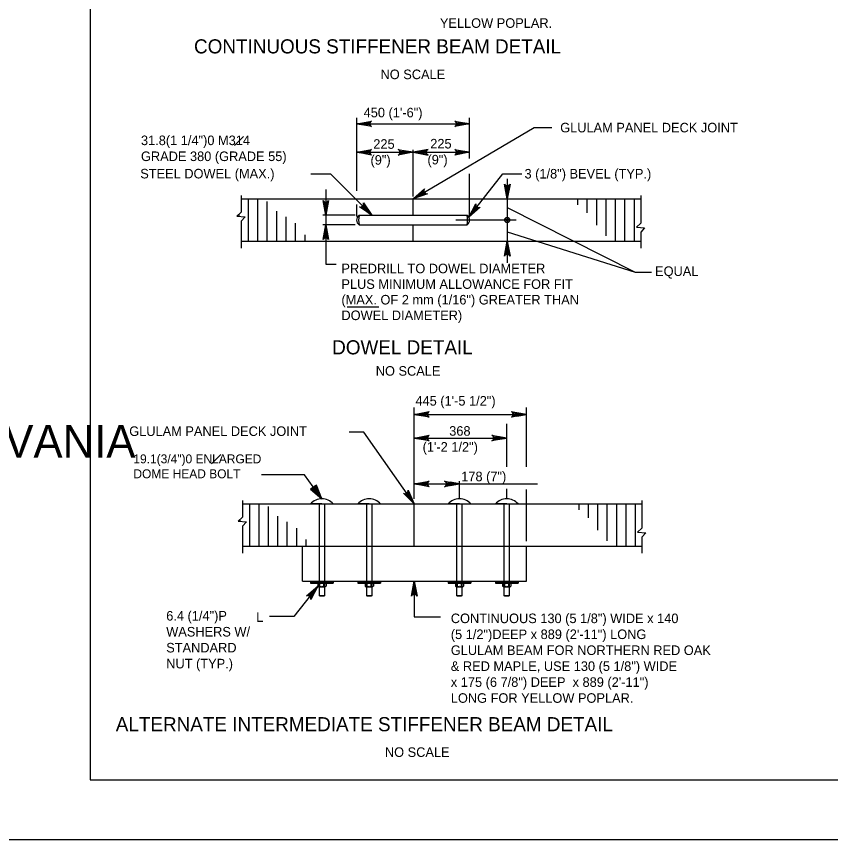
# Model space of a CAD drawing. Extents: x -8 to 75, y -110 to 0.
# Drawn here: x 34.83 to 45.04, y -88 to -77.67 of the extents above; entities that cross this region are included whole.
import ezdxf

# ---------------------------------------------------------------- set-up
doc = ezdxf.new("R2010")
doc.units = 0
for name, color, linetype in [('1', 7, 'Continuous'), ('2', 7, 'Continuous'), ('3', 7, 'Continuous'), ('5', 7, 'Continuous'), ('63', 7, 'Continuous')]:
    doc.layers.add(name, color=color, linetype=linetype)

msp = doc.modelspace()

# ---------------------------------------------------------------- linework, layer by layer
at = {"layer": '1'}
msp.add_lwpolyline([(35.75, -87.25), (67.25, -87.25), (67.25, -66.75), (35.75, -66.75)], close=True, dxfattribs=at)
at = {"layer": '2'}
for p, q in [((37.647, -79.916), (37.647, -80.126)), ((42.661, -79.916), (42.661, -80.264)), ((37.647, -79.959), (42.661, -79.959)), ((39.804, -80.166), (39.804, -79.959)), ((37.647, -80.126), (37.592, -80.178)), ((37.592, -80.178), (37.696, -80.184)), ((37.696, -80.184), (37.647, -80.239)), ((37.647, -80.239), (37.647, -80.579)), ((39.804, -80.491), (39.804, -80.284)), ((42.661, -80.264), (42.606, -80.316)), ((42.606, -80.316), (42.71, -80.322)), ((42.71, -80.322), (42.661, -80.376)), ((42.661, -80.376), (42.661, -80.579)), ((37.647, -80.491), (42.661, -80.491)), ((38.442, -83.422), (37.899, -83.422)), ((38.659, -83.723), (38.442, -83.422)), ((37.662, -83.743), (37.662, -83.954)), ((42.676, -83.743), (42.676, -84.091)), ((37.662, -83.787), (42.676, -83.787)), ((38.659, -83.787), (38.517, -83.787)), ((38.628, -84.94), (38.628, -83.787)), ((38.659, -83.787), (38.802, -83.787)), ((38.691, -83.787), (38.691, -84.94)), ((39.221, -84.94), (39.221, -83.787)), ((39.284, -83.787), (39.284, -84.94)), ((39.819, -84.319), (39.819, -83.787)), ((40.354, -84.94), (40.354, -83.787)), ((40.417, -83.787), (40.417, -84.94)), ((40.948, -84.94), (40.948, -83.787)), ((41.011, -83.787), (41.011, -84.94)), ((37.662, -83.954), (37.607, -84.006)), ((37.607, -84.006), (37.711, -84.012)), ((37.711, -84.012), (37.662, -84.066)), ((37.662, -84.066), (37.662, -84.407)), ((42.676, -84.091), (42.621, -84.144)), ((42.621, -84.144), (42.725, -84.149)), ((42.725, -84.149), (42.676, -84.204)), ((42.676, -84.204), (42.676, -84.407)), ((37.662, -84.319), (42.676, -84.319)), ((38.414, -84.759), (38.414, -84.319)), ((41.225, -84.759), (41.225, -84.319)), ((38.414, -84.759), (41.225, -84.759)), ((38.711, -84.783), (38.607, -84.783)), ((38.607, -84.783), (38.607, -84.819)), ((38.635, -84.827), (38.635, -84.783)), ((38.684, -84.827), (38.684, -84.783)), ((38.711, -84.783), (38.711, -84.819)), ((39.2, -84.783), (39.2, -84.819)), ((39.305, -84.783), (39.2, -84.783)), ((39.228, -84.827), (39.228, -84.783)), ((39.277, -84.827), (39.277, -84.783)), ((39.305, -84.783), (39.305, -84.819)), ((40.334, -84.783), (40.334, -84.819)), ((40.438, -84.783), (40.334, -84.783)), ((40.361, -84.827), (40.361, -84.783)), ((40.41, -84.827), (40.41, -84.783)), ((40.438, -84.783), (40.438, -84.819)), ((40.927, -84.783), (40.927, -84.819)), ((41.031, -84.783), (40.927, -84.783)), ((40.955, -84.827), (40.955, -84.783)), ((41.004, -84.827), (41.004, -84.783)), ((41.031, -84.783), (41.031, -84.819)), ((38.607, -84.819), (38.622, -84.827)), ((38.622, -84.827), (38.696, -84.827)), ((38.696, -84.827), (38.711, -84.819)), ((39.2, -84.819), (39.215, -84.827)), ((39.215, -84.827), (39.29, -84.827)), ((39.29, -84.827), (39.305, -84.819)), ((40.334, -84.819), (40.349, -84.827)), ((40.349, -84.827), (40.423, -84.827)), ((40.423, -84.827), (40.438, -84.819)), ((40.927, -84.819), (40.942, -84.827)), ((40.942, -84.827), (41.016, -84.827)), ((41.016, -84.827), (41.031, -84.819)), ((38.691, -84.94), (38.628, -84.94)), ((38.636, -84.947), (38.628, -84.94)), ((38.683, -84.947), (38.636, -84.947)), ((38.691, -84.94), (38.683, -84.947)), ((39.229, -84.947), (39.221, -84.94)), ((39.284, -84.94), (39.221, -84.94)), ((39.276, -84.947), (39.229, -84.947)), ((39.284, -84.94), (39.276, -84.947)), ((40.362, -84.947), (40.354, -84.94)), ((40.417, -84.94), (40.354, -84.94)), ((40.409, -84.947), (40.362, -84.947)), ((40.417, -84.94), (40.409, -84.947)), ((40.956, -84.947), (40.948, -84.94)), ((41.011, -84.94), (40.948, -84.94)), ((41.003, -84.947), (40.956, -84.947)), ((41.011, -84.94), (41.003, -84.947))]:
    msp.add_line(p, q, dxfattribs=at)
msp.add_lwpolyline([(40.504, -80.191), (40.929, -79.645), (41.17, -79.645)], dxfattribs=at)
for points in [[(40.504, -80.191), (40.508, -80.188), (40.506, -80.186)], [(38.659, -83.723), (38.59, -83.551), (38.517, -83.604)]]:
    msp.add_lwpolyline(points, close=True, dxfattribs=at)
for centre, radius, start, end in [((38.659, -83.915), 0.192, 41.8701, 138.1299), ((38.633, -84.784), 0.0434, 233, 307), ((38.685, -84.784), 0.0434, 233, 307), ((39.227, -84.784), 0.0434, 233, 307), ((39.279, -84.784), 0.0434, 233, 307), ((40.36, -84.784), 0.0434, 233, 307), ((40.412, -84.784), 0.0434, 233, 307), ((40.953, -84.784), 0.0434, 233, 307), ((41.005, -84.784), 0.0434, 233, 307)]:
    msp.add_arc(centre, radius, start, end, dxfattribs=at)
at = {"layer": '3'}
for p, q in [((39.096, -79.857), (39.096, -78.944)), ((39.096, -79.018), (40.513, -79.018)), ((40.513, -79.454), (40.513, -78.944)), ((37.56, -79.289), (37.673, -79.177)), ((39.096, -79.374), (40.513, -79.374)), ((39.804, -79.931), (39.804, -79.342)), ((38.522, -79.645), (38.767, -79.645)), ((39.286, -80.166), (38.767, -79.644)), ((40.513, -80.179), (40.513, -79.646)), ((40.985, -79.709), (40.985, -80.761)), ((38.708, -79.843), (38.708, -80.779)), ((39.096, -80.179), (39.096, -80.031)), ((40.985, -80.069), (42.591, -80.879)), ((39.076, -80.166), (38.671, -80.166)), ((41.097, -80.225), (40.34, -80.225)), ((39.076, -80.284), (38.669, -80.284)), ((40.985, -80.374), (42.591, -80.879)), ((38.708, -80.779), (38.84, -80.779)), ((42.591, -80.879), (42.796, -80.879)), ((38.978, -81.313), (39.373, -81.313)), ((37.274, -83.283), (37.389, -83.169)), ((38.306, -85.201), (38, -85.201)), ((39.819, -85.207), (40.148, -85.207))]:
    msp.add_line(p, q, dxfattribs=at)
for points in [[(39.096, -79.018), (39.282, -78.983), (39.268, -78.993), (39.26, -79.006), (39.258, -79.018), (39.26, -79.031), (39.268, -79.043), (39.282, -79.053), (39.096, -79.018), (39.268, -79.043), (39.26, -79.031), (39.096, -79.018), (39.258, -79.018), (39.26, -79.006), (39.096, -79.018), (39.268, -78.993)], [(40.513, -79.018), (40.326, -79.053), (40.341, -79.043), (40.348, -79.031), (40.35, -79.018), (40.348, -79.006), (40.341, -78.993), (40.326, -78.983), (40.513, -79.018), (40.341, -78.993), (40.348, -79.006), (40.513, -79.018), (40.35, -79.018), (40.348, -79.031), (40.513, -79.018), (40.341, -79.043)], [(39.804, -79.959), (41.323, -79.065), (41.544, -79.065)], [(39.096, -79.374), (39.282, -79.339), (39.268, -79.349), (39.26, -79.361), (39.258, -79.374), (39.26, -79.386), (39.268, -79.399), (39.282, -79.409), (39.096, -79.374), (39.268, -79.399), (39.26, -79.386), (39.096, -79.374), (39.258, -79.374), (39.26, -79.361), (39.096, -79.374), (39.268, -79.349)], [(39.804, -79.374), (39.618, -79.409), (39.632, -79.399), (39.639, -79.386), (39.642, -79.374), (39.639, -79.361), (39.632, -79.349), (39.618, -79.339), (39.804, -79.374), (39.632, -79.349), (39.639, -79.361), (39.804, -79.374), (39.642, -79.374), (39.639, -79.386), (39.804, -79.374), (39.632, -79.399)], [(39.804, -79.374), (39.991, -79.409), (39.976, -79.399), (39.969, -79.386), (39.967, -79.374), (39.969, -79.361), (39.976, -79.349), (39.991, -79.339), (39.804, -79.374), (39.976, -79.349), (39.969, -79.361), (39.804, -79.374), (39.967, -79.374), (39.969, -79.386), (39.804, -79.374), (39.976, -79.399)], [(40.513, -79.374), (40.326, -79.409), (40.341, -79.399), (40.348, -79.386), (40.35, -79.374), (40.348, -79.361), (40.341, -79.349), (40.326, -79.339), (40.513, -79.374), (40.341, -79.349), (40.348, -79.361), (40.513, -79.374), (40.35, -79.374), (40.348, -79.386), (40.513, -79.374), (40.341, -79.399)], [(39.804, -79.959), (39.947, -79.835), (39.94, -79.851), (39.94, -79.865), (39.944, -79.877), (39.952, -79.887), (39.965, -79.894), (39.983, -79.895), (39.804, -79.959), (39.965, -79.894), (39.952, -79.887), (39.804, -79.959), (39.944, -79.877), (39.94, -79.865), (39.804, -79.959), (39.94, -79.851)], [(40.985, -79.96), (40.95, -79.773), (40.96, -79.788), (40.973, -79.795), (40.985, -79.797), (40.998, -79.795), (41.01, -79.788), (41.02, -79.773), (40.985, -79.96), (41.01, -79.788), (40.998, -79.795), (40.985, -79.96), (40.985, -79.797), (40.973, -79.795), (40.985, -79.96), (40.96, -79.788)], [(38.708, -80.166), (38.673, -79.98), (38.683, -79.994), (38.696, -80.001), (38.708, -80.004), (38.721, -80.001), (38.733, -79.994), (38.743, -79.98), (38.708, -80.166), (38.733, -79.994), (38.721, -80.001), (38.708, -80.166), (38.708, -80.004), (38.696, -80.001), (38.708, -80.166), (38.683, -79.994)], [(39.286, -80.166), (39.13, -80.059), (39.147, -80.062), (39.161, -80.058), (39.172, -80.051), (39.179, -80.041), (39.183, -80.027), (39.18, -80.009), (39.286, -80.166), (39.183, -80.027), (39.179, -80.041), (39.286, -80.166), (39.172, -80.051), (39.161, -80.058), (39.286, -80.166), (39.147, -80.062)], [(40.504, -80.191), (40.591, -80.022), (40.59, -80.04), (40.595, -80.053), (40.604, -80.063), (40.615, -80.069), (40.629, -80.07), (40.646, -80.065), (40.504, -80.191), (40.629, -80.07), (40.615, -80.069), (40.504, -80.191), (40.604, -80.063), (40.595, -80.053), (40.504, -80.191), (40.59, -80.04)], [(38.708, -80.284), (38.743, -80.471), (38.733, -80.456), (38.721, -80.449), (38.708, -80.447), (38.696, -80.449), (38.683, -80.456), (38.673, -80.471), (38.708, -80.284), (38.683, -80.456), (38.696, -80.449), (38.708, -80.284), (38.708, -80.447), (38.721, -80.449), (38.708, -80.284), (38.733, -80.456)], [(40.985, -80.491), (41.02, -80.677), (41.01, -80.663), (40.998, -80.656), (40.985, -80.653), (40.973, -80.656), (40.96, -80.663), (40.95, -80.677), (40.985, -80.491), (40.96, -80.663), (40.973, -80.656), (40.985, -80.491), (40.985, -80.653), (40.998, -80.656), (40.985, -80.491), (41.01, -80.663)], [(39.819, -83.787), (39.186, -82.888), (39.001, -82.888)], [(38.659, -83.723), (38.522, -83.593), (38.538, -83.598), (38.553, -83.597), (38.564, -83.591), (38.573, -83.582), (38.579, -83.569), (38.578, -83.552), (38.659, -83.723), (38.579, -83.569), (38.573, -83.582), (38.659, -83.723), (38.564, -83.591), (38.553, -83.597), (38.659, -83.723), (38.538, -83.598)], [(39.819, -83.787), (39.683, -83.655), (39.7, -83.661), (39.714, -83.66), (39.725, -83.654), (39.734, -83.645), (39.74, -83.632), (39.74, -83.614), (39.819, -83.787), (39.74, -83.632), (39.734, -83.645), (39.819, -83.787), (39.725, -83.654), (39.714, -83.66), (39.819, -83.787), (39.7, -83.661)], [(39.819, -84.759), (39.854, -84.946), (39.844, -84.931), (39.832, -84.924), (39.819, -84.922), (39.807, -84.924), (39.794, -84.931), (39.784, -84.946), (39.819, -84.759), (39.794, -84.931), (39.807, -84.924), (39.819, -84.759), (39.819, -84.922), (39.832, -84.924), (39.819, -84.759), (39.844, -84.931)], [(39.819, -84.759), (39.819, -85.207)], [(38.607, -84.819), (38.306, -85.201)], [(38.607, -84.819), (38.519, -84.987), (38.52, -84.969), (38.515, -84.956), (38.506, -84.946), (38.495, -84.94), (38.481, -84.938), (38.464, -84.943), (38.607, -84.819), (38.481, -84.938), (38.495, -84.94), (38.607, -84.819), (38.506, -84.946), (38.515, -84.956), (38.607, -84.819), (38.52, -84.969)]]:
    msp.add_lwpolyline(points, dxfattribs=at)
for points in [[(39.804, -79.959), (39.809, -79.958), (39.808, -79.956)], [(39.22, -80.072), (39.193, -80.099), (39.286, -80.166)], [(39.819, -83.787), (39.817, -83.783), (39.815, -83.785)], [(39.819, -84.759), (39.818, -84.764), (39.82, -84.764)], [(38.607, -84.819), (38.603, -84.822), (38.605, -84.823)]]:
    msp.add_lwpolyline(points, close=True, dxfattribs=at)
for radius in [0.0333, 0.0167]:
    msp.add_circle((40.985, -80.225), radius, dxfattribs=at)
at = {"layer": '5'}
for p, q in [((37.738, -80.491), (37.738, -79.959)), ((37.856, -80.491), (37.856, -79.959)), ((37.974, -80.491), (37.974, -79.994)), ((41.872, -80.034), (41.872, -79.959)), ((41.99, -80.136), (41.99, -79.959)), ((42.108, -80.289), (42.108, -79.959)), ((42.226, -80.425), (42.226, -79.959)), ((42.344, -80.489), (42.344, -79.959)), ((42.462, -80.491), (42.462, -79.959)), ((42.581, -80.491), (42.581, -79.959)), ((37.62, -80.18), (37.62, -80.152)), ((38.092, -80.491), (38.092, -80.114)), ((38.21, -80.491), (38.21, -80.185)), ((39.126, -80.166), (40.482, -80.166)), ((38.328, -80.491), (38.328, -80.263)), ((39.125, -80.284), (40.483, -80.284)), ((42.699, -80.335), (42.699, -80.321)), ((38.447, -80.49), (38.447, -80.409)), ((38.565, -80.49), (38.565, -80.486)), ((39.819, -83.725), (39.819, -82.576)), ((41.225, -83.323), (41.225, -82.577)), ((41.225, -82.966), (41.225, -82.577)), ((39.819, -82.665), (41.225, -82.665)), ((41.225, -82.665), (41.225, -82.665)), ((39.819, -83.725), (39.819, -82.784)), ((40.979, -83.007), (40.979, -82.784)), ((40.979, -83.323), (40.979, -82.925)), ((39.819, -82.962), (40.979, -82.962)), ((40.979, -82.962), (40.979, -82.962)), ((39.819, -83.725), (39.819, -83.359)), ((39.819, -83.537), (41.363, -83.537)), ((40.386, -83.726), (40.386, -83.504)), ((40.386, -83.537), (40.386, -83.537)), ((40.979, -83.726), (40.979, -83.599)), ((41.225, -84.257), (41.225, -83.608)), ((37.753, -84.318), (37.753, -83.787)), ((37.871, -84.318), (37.871, -83.787)), ((37.989, -84.318), (37.989, -83.821)), ((39.253, -83.787), (39.11, -83.787)), ((39.253, -83.787), (39.395, -83.787)), ((39.819, -83.787), (39.819, -83.787)), ((40.386, -83.787), (40.243, -83.787)), ((40.386, -83.787), (40.529, -83.787)), ((40.386, -83.787), (40.386, -83.787)), ((40.979, -83.787), (40.837, -83.787)), ((40.979, -83.787), (41.122, -83.787)), ((40.979, -83.787), (40.979, -83.787)), ((41.887, -83.862), (41.887, -83.787)), ((42.005, -83.963), (42.005, -83.787)), ((42.123, -84.117), (42.123, -83.787)), ((42.241, -84.253), (42.241, -83.787)), ((42.359, -84.316), (42.359, -83.787)), ((42.477, -84.319), (42.477, -83.787)), ((42.596, -84.319), (42.596, -83.787)), ((37.635, -84.007), (37.635, -83.979)), ((38.107, -84.318), (38.107, -83.941)), ((38.225, -84.318), (38.225, -84.013)), ((38.343, -84.318), (38.343, -84.091)), ((42.714, -84.162), (42.714, -84.149)), ((38.462, -84.318), (38.462, -84.236)), ((38.58, -84.318), (38.58, -84.313)), ((41.225, -84.319), (41.225, -84.319)), ((38.517, -84.759), (38.517, -84.783)), ((38.517, -84.771), (38.802, -84.771)), ((38.517, -84.783), (38.802, -84.783)), ((38.802, -84.759), (38.802, -84.783)), ((39.11, -84.759), (39.11, -84.783)), ((39.11, -84.771), (39.395, -84.771)), ((39.11, -84.783), (39.395, -84.783)), ((39.395, -84.759), (39.395, -84.783)), ((40.243, -84.759), (40.243, -84.783)), ((40.243, -84.771), (40.529, -84.771)), ((40.243, -84.783), (40.529, -84.783)), ((40.529, -84.759), (40.529, -84.783)), ((40.837, -84.759), (40.837, -84.783)), ((40.837, -84.771), (41.122, -84.771)), ((40.837, -84.783), (41.122, -84.783)), ((41.122, -84.759), (41.122, -84.783))]:
    msp.add_line(p, q, dxfattribs=at)
for points in [[(39.819, -82.665), (40.006, -82.63), (39.991, -82.64), (39.984, -82.653), (39.982, -82.665), (39.984, -82.678), (39.991, -82.69), (40.006, -82.7), (39.819, -82.665), (39.991, -82.69), (39.984, -82.678), (39.819, -82.665), (39.982, -82.665), (39.984, -82.653), (39.819, -82.665), (39.991, -82.64)], [(41.225, -82.665), (41.038, -82.7), (41.053, -82.69), (41.06, -82.678), (41.062, -82.665), (41.06, -82.653), (41.053, -82.64), (41.038, -82.63), (41.225, -82.665), (41.053, -82.64), (41.06, -82.653), (41.225, -82.665), (41.062, -82.665), (41.06, -82.678), (41.225, -82.665), (41.053, -82.69)], [(39.819, -82.962), (40.006, -82.927), (39.991, -82.937), (39.984, -82.949), (39.982, -82.962), (39.984, -82.974), (39.991, -82.987), (40.006, -82.997), (39.819, -82.962), (39.991, -82.987), (39.984, -82.974), (39.819, -82.962), (39.982, -82.962), (39.984, -82.949), (39.819, -82.962), (39.991, -82.937)], [(40.979, -82.962), (40.793, -82.997), (40.807, -82.987), (40.814, -82.974), (40.817, -82.962), (40.814, -82.949), (40.807, -82.937), (40.793, -82.927), (40.979, -82.962), (40.807, -82.937), (40.814, -82.949), (40.979, -82.962), (40.817, -82.962), (40.814, -82.974), (40.979, -82.962), (40.807, -82.987)], [(39.819, -83.537), (40.006, -83.502), (39.991, -83.512), (39.984, -83.524), (39.982, -83.537), (39.984, -83.549), (39.991, -83.562), (40.006, -83.572), (39.819, -83.537), (39.991, -83.562), (39.984, -83.549), (39.819, -83.537), (39.982, -83.537), (39.984, -83.524), (39.819, -83.537), (39.991, -83.512)], [(40.386, -83.537), (40.199, -83.572), (40.214, -83.562), (40.221, -83.549), (40.223, -83.537), (40.221, -83.524), (40.214, -83.512), (40.199, -83.502), (40.386, -83.537), (40.214, -83.512), (40.221, -83.524), (40.386, -83.537), (40.223, -83.537), (40.221, -83.549), (40.386, -83.537), (40.214, -83.562)]]:
    msp.add_lwpolyline(points, dxfattribs=at)
for points in [[(39.937, -82.645), (39.937, -82.685), (39.819, -82.665)], [(41.107, -82.645), (41.107, -82.685), (41.225, -82.665)], [(39.937, -82.942), (39.937, -82.981), (39.819, -82.962)], [(40.861, -82.942), (40.861, -82.981), (40.979, -82.962)], [(39.937, -83.517), (39.937, -83.556), (39.819, -83.537)], [(40.268, -83.517), (40.268, -83.556), (40.386, -83.537)]]:
    msp.add_lwpolyline(points, close=True, dxfattribs=at)
for centre, radius, start, end in [((39.168, -80.226), 0.0728, 125.2575, 233.7233), ((39.425, -80.228), 0.305, 168.3368, 190.6439), ((40.44, -80.226), 0.0728, 306.2767, 54.7425), ((40.183, -80.228), 0.305, 349.3561, 11.6632), ((39.253, -83.915), 0.192, 41.8701, 138.1299), ((40.386, -83.915), 0.192, 41.8701, 138.1299), ((40.979, -83.915), 0.192, 41.8701, 138.1299)]:
    msp.add_arc(centre, radius, start, end, dxfattribs=at)
at = {"layer": '63'}
msp.add_lwpolyline([(34, -88), (68, -88), (68, -66), (34, -66)], close=True, dxfattribs=at)

# ---------------------------------------------------------------- texts
at = {"layer": '1'}
msp.add_text('COMMONWEALTH OF PENNSYLVANIA', height=0.41038, dxfattribs=at).set_placement((26.196, -83.208))
at = {"layer": '3'}
for s, height, p in [('YELLOW POPLAR.', 0.12, (40.14, -77.813)), ('CONTINUOUS STIFFENER BEAM DETAIL', 0.17717, (37.054, -78.134)), ('NO SCALE', 0.12, (39.395, -78.457)), ('450 (1\'-6")', 0.12, (39.183, -78.936)), ('GLULAM PANEL DECK JOINT', 0.12, (41.65, -79.125)), ('31.8(1 1/4")0 M314', 0.12, (36.388, -79.285)), ('225', 0.12, (39.304, -79.331)), ('225', 0.12, (40.019, -79.327)), ('GRADE 380 (GRADE 55)', 0.12, (36.388, -79.485)), ('(9")', 0.12, (39.269, -79.531)), ('(9")', 0.12, (39.984, -79.527)), ('STEEL DOWEL (MAX.)', 0.12, (36.379, -79.703)), ('3 (1/8") BEVEL (TYP.)', 0.12, (41.202, -79.704)), ('PREDRILL TO DOWEL DIAMETER', 0.12, (38.904, -80.893)), ('EQUAL', 0.12, (42.841, -80.927)), ('PLUS MINIMUM ALLOWANCE FOR FIT', 0.12, (38.904, -81.089)), ('(MAX. OF 2 mm (1/16") GREATER THAN', 0.12, (38.904, -81.285)), ('DOWEL DIAMETER)', 0.12, (38.904, -81.481)), ('DOWEL DETAIL', 0.17717, (38.788, -81.911)), ('NO SCALE', 0.12, (39.335, -82.179)), ('GLULAM PANEL DECK JOINT', 0.12, (36.241, -82.935)), ('19.1(3/4")0 ENLARGED', 0.11233, (36.293, -83.279)), ('DOME HEAD BOLT', 0.11233, (36.293, -83.466)), ('6.4 (1/4")P', 0.12, (36.705, -85.252)), ('L', 0.12, (37.835, -85.268)), ('CONTINUOUS 130 (5 1/8") WIDE x 140', 0.12, (40.277, -85.284)), ('WASHERS W/ ', 0.12, (36.705, -85.452)), ('(5 1/2")DEEP x 889 (2\'-11") LONG', 0.12, (40.277, -85.484)), ('STANDARD', 0.12, (36.705, -85.652)), ('GLULAM BEAM FOR NORTHERN RED OAK', 0.12, (40.277, -85.684)), ('NUT (TYP.)', 0.12, (36.705, -85.852)), ('& RED MAPLE, USE 130 (5 1/8") WIDE', 0.12, (40.277, -85.884)), ('x 175 (6 7/8") DEEP  x 889 (2\'-11")', 0.12, (40.277, -86.084)), ('LONG FOR YELLOW POPLAR.', 0.12, (40.277, -86.284)), ('ALTERNATE INTERMEDIATE STIFFENER BEAM DETAIL', 0.17717, (36.072, -86.641)), ('NO SCALE', 0.12, (39.45, -86.963))]:
    msp.add_text(s, height=height, dxfattribs=at).set_placement(p)
at = {"layer": '5'}
for s, p in [('445 (1\'-5 1/2")', (39.833, -82.554)), ('368', (40.257, -82.932)), ('(1\'-2 1/2")', (39.923, -83.132)), ('178 (7")', (40.408, -83.503))]:
    msp.add_text(s, height=0.12, dxfattribs=at).set_placement(p)

doc.saveas('drawing.dxf')
